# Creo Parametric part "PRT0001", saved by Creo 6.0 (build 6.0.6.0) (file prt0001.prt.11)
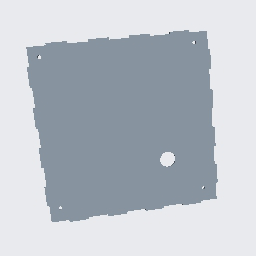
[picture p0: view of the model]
Units: Inch lbm Second (Pro/E Default); INCH, POUND, SECS

Created from: INLBS_PART_SOLID.PRT

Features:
  1. datum plane "RIGHT"
  2. datum plane "TOP"
  3. datum plane "FRONT"
  4. coordinate system
  5. sketch "Sketch 1"
  6. extrusion "Extrude 1"
  7. sketch "Sketch 2"
  8. extruded cut "Extrude 2"
  9. sketch "Sketch 3"
  10. extruded cut "Extrude 3"
  11. sketch "Sketch 4"
  12. extruded cut "Extrude 4"

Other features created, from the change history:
  extrusion "Extrude 2" (2 times)
  mirror "Mirror 1"

Surfaces: 70 plane, 5 cylinder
